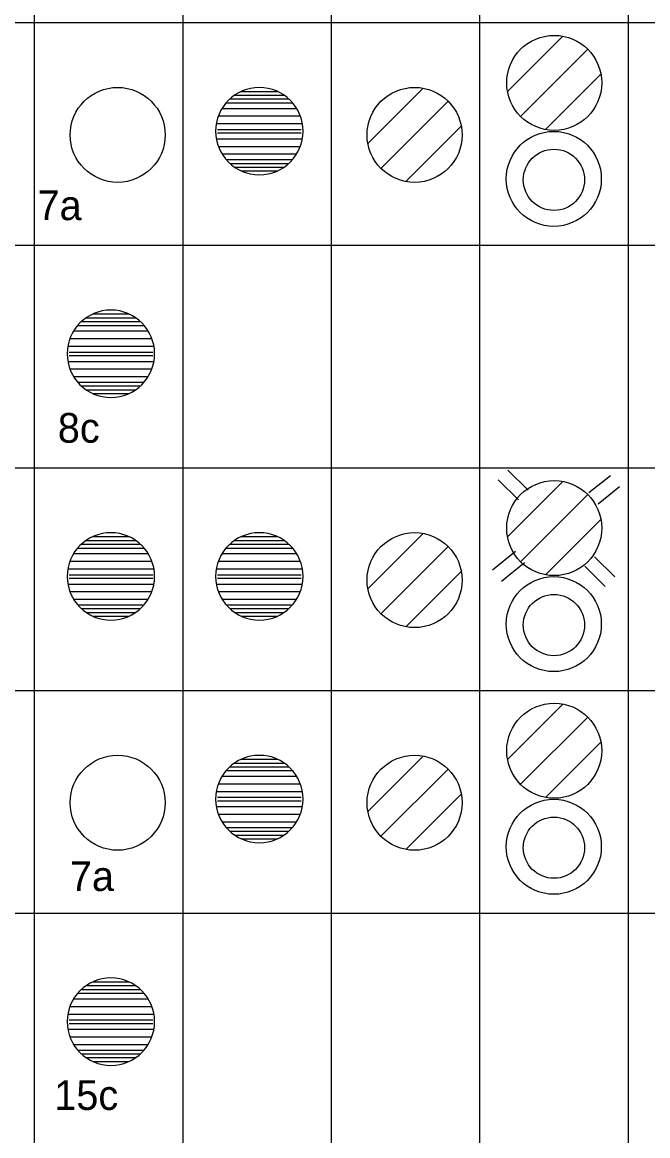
# Model space of a CAD drawing. Extents: x -28 to 822, y 61 to 665.
# Drawn here: x 499.8 to 541.9, y 171.7 to 246.8 of the extents above; entities that cross this region are included whole.
import ezdxf

# ---------------------------------------------------------------- set-up
doc = ezdxf.new("R2010")
doc.units = 0
doc.layers.add('KOLEJIŠTĚ', color=7, linetype='Continuous')
doc.layers.add('nové', color=7, linetype='Continuous')

# ---------------------------------------------------------------- blocks, each defined once
blk = doc.blocks.new('ZT95')
for p, q in [((2.793, 4.073), (0.927, 2.207)), ((3.631, 3.631), (1.369, 1.369)), ((4.073, 2.793), (2.207, 0.927))]:
    blk.add_line(p, q)
blk.add_circle((2.5, 2.5), 1.6)
blk = doc.blocks.new('HR6')
for p, q in [((-1.304, 1.895), (1.304, 1.895)), ((-0.95, 2.095), (0.95, 2.095)), ((-1.962, 1.2), (1.962, 1.2)), ((-1.748, 1.495), (1.748, 1.495)), ((-1.555, 1.695), (1.555, 1.695)), ((-2.156, 0.8), (2.156, 0.8)), ((-2.265, 0.4), (2.265, 0.4)), ((-2.2, 0.09), (2.2, 0.09)), ((-2.265, -0.4), (2.265, -0.4)), ((-2.2, -0.09), (2.2, -0.09)), ((-2.156, -0.8), (2.156, -0.8)), ((-1.962, -1.2), (1.962, -1.2)), ((-1.748, -1.495), (1.748, -1.495)), ((-1.555, -1.695), (1.555, -1.695)), ((-1.304, -1.895), (1.304, -1.895)), ((-0.95, -2.095), (0.95, -2.095))]:
    blk.add_line(p, q)
for start, end in [(0, 180), (180, 0)]:
    blk.add_arc((0, 0), 2.3, start, end)
blk = doc.blocks.new('ZT94')
at = {"xscale": 0.6400000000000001, "yscale": 0.6400000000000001}
blk.add_blockref('HR6', (2.5, 2.5), dxfattribs=at)

msp = doc.modelspace()

# ---------------------------------------------------------------- linework, layer by layer
for p, q in [((500.616, 381.738), (500.616, 111.738)), ((510.616, 381.738), (510.616, 111.738)), ((520.616, 381.738), (520.616, 111.738)), ((530.616, 381.738), (530.616, 111.738)), ((5.068, 246.738), (540.616, 246.738)), ((5.068, 246.738), (540.616, 246.738)), ((339.087, 231.738), (540.616, 231.738)), ((5.068, 216.738), (540.616, 216.738)), ((533.88, 215.239), (532.528, 216.591)), ((537.978, 215.074), (539.426, 216.232)), ((533.237, 214.577), (531.872, 215.942)), ((538.594, 214.313), (540.042, 215.471)), ((531.483, 209.877), (533.044, 211.127)), ((532.089, 209.109), (533.651, 210.358)), ((539.076, 208.738), (537.705, 210.109)), ((539.725, 209.394), (538.367, 210.752)), ((5.068, 201.738), (540.616, 201.738)), ((5.068, 201.738), (540.616, 201.738)), ((5.068, 201.738), (540.616, 201.738)), ((54.092, 201.738), (540.616, 201.738)), ((348.116, 186.738), (540.616, 186.738))]:
    msp.add_line(p, q)
for centre, radius in [((506.237, 239.173), 3.2), ((535.616, 236.208), 3.2), ((535.624, 236.145), 2.063), ((535.616, 206.208), 3.2), ((535.624, 206.145), 2.063), ((506.237, 194.173), 3.2), ((535.616, 191.208), 3.2), ((535.624, 191.145), 2.063)]:
    msp.add_circle(centre, radius)
at = {"layer": 'nové'}
for p, q in [((540.616, 381.738), (540.616, 111.738)), ((540.616, 246.738), (590.616, 246.738)), ((540.616, 231.738), (590.616, 231.738)), ((540.616, 216.738), (590.616, 216.738)), ((540.616, 201.738), (590.616, 201.738)), ((540.616, 186.738), (590.616, 186.738))]:
    msp.add_line(p, q, dxfattribs=at)

# ---------------------------------------------------------------- block references
at = {"layer": 'KOLEJIŠTĚ', "xscale": 2, "yscale": 2}
for name, p in [('ZT95', (530.643, 237.677)), ('ZT94', (510.781, 234.424)), ('ZT95', (521.237, 234.173)), ('ZT94', (500.781, 219.424)), ('ZT95', (530.643, 207.677)), ('ZT94', (500.781, 204.424)), ('ZT94', (510.781, 204.424)), ('ZT95', (521.237, 204.173)), ('ZT95', (530.643, 192.677)), ('ZT94', (510.781, 189.424)), ('ZT95', (521.237, 189.173)), ('ZT94', (500.781, 174.424))]:
    msp.add_blockref(name, p, dxfattribs=at)

# ---------------------------------------------------------------- texts
for s, p in [('7a', (500.836, 233.431)), ('8c', (502.204, 218.434)), ('7a', (503.014, 188.23)), ('15c', (501.962, 173.475))]:
    msp.add_text(s, height=2).set_placement(p)

doc.saveas('drawing.dxf')
